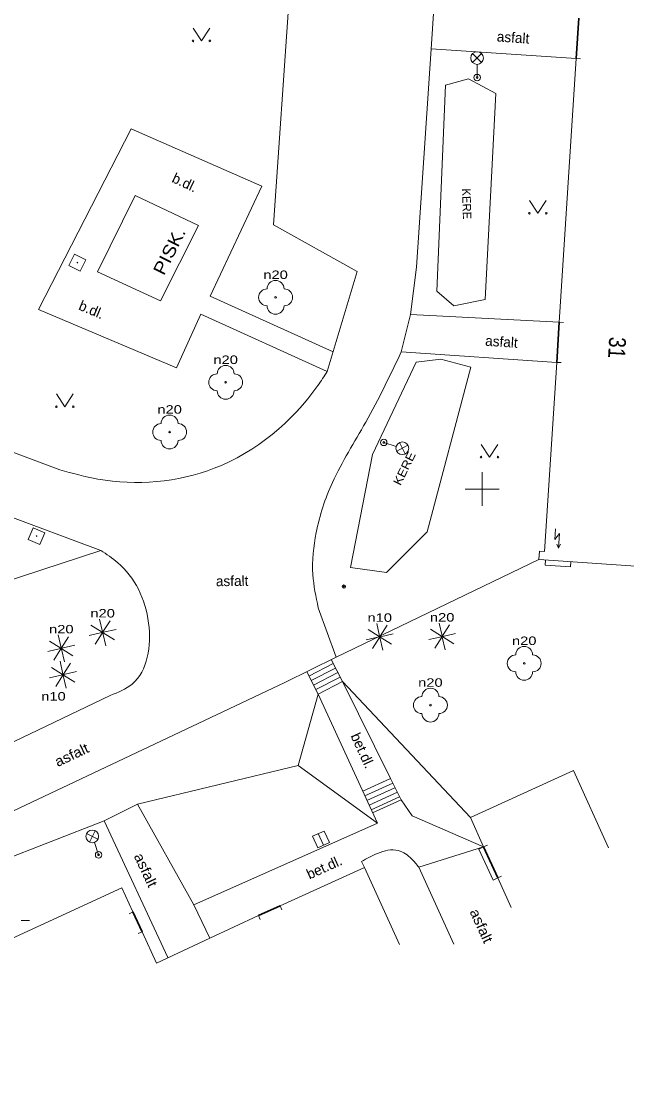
# Model space of a CAD drawing. Extents: x -670514 to -669423, y -1130798 to -1130123.
# Drawn here: x -670227.2 to -670191.5, y -1130334.6 to -1130272.3 of the extents above; entities that cross this region are included whole.
import ezdxf
from ezdxf.enums import TextEntityAlignment as Align

# ---------------------------------------------------------------- set-up
doc = ezdxf.new("R2010")
doc.units = 0
doc.header["$LTSCALE"] = 0.24
for name, color, linetype, lineweight in [('10', 7, 'Continuous', 13), ('11', 7, 'Continuous', 13), ('14', 7, 'Continuous', 13), ('21', 7, 'Continuous', 13), ('22', 7, 'Continuous', 13), ('24', 7, 'Continuous', 13), ('25', 7, 'Continuous', 13), ('26', 7, 'Continuous', 13), ('27', 7, 'Continuous', 13), ('28', 7, 'Continuous', 13), ('33', 7, 'Continuous', 13), ('36', 7, 'Continuous', 13), ('5', 7, 'Continuous', 13), ('6', 7, 'Continuous', 13), ('61', 7, 'Continuous', 13)]:
    doc.layers.add(name, color=color, linetype=linetype, lineweight=lineweight)
for name, color, linetype in [('40', 7, 'Continuous'), ('42', 7, 'Continuous'), ('44', 7, 'Continuous'), ('47', 7, 'Continuous')]:
    doc.layers.add(name, color=color, linetype=linetype)

msp = doc.modelspace()

# ---------------------------------------------------------------- linework, layer by layer
at = {"layer": '10'}
for p, q in [((-670212.326, -1130284.389), (-670210.077, -1130251.897)), ((-670203.011, -1130273.982), (-670202.849, -1130271.587)), ((-670203.011, -1130273.982), (-670194.444, -1130274.555)), ((-670212.326, -1130284.389), (-670207.379, -1130287.133)), ((-670266.711, -1130287.197), (-670222.534, -1130303.625)), ((-670209.153, -1130293.051), (-670207.379, -1130287.133)), ((-670204.781, -1130291.893), (-670204.232, -1130289.675)), ((-670204.232, -1130289.675), (-670195.447, -1130290.143)), ((-670224.952, -1130298.862), (-670248.531, -1130290.145)), ((-670204.781, -1130291.893), (-670195.588, -1130292.511)), ((-670208.8, -1130310.316), (-670210.24, -1130311.053)), ((-670208.254, -1130311.385), (-670208.918, -1130310.085)), ((-670209.694, -1130312.122), (-670210.369, -1130310.801)), ((-670208.664, -1130310.583), (-670210.104, -1130311.32)), ((-670208.527, -1130310.85), (-670209.967, -1130311.587)), ((-670208.391, -1130311.117), (-670209.83, -1130311.854)), ((-670208.254, -1130311.385), (-670209.694, -1130312.122)), ((-670260.508, -1130330.656), (-670221.974, -1130312.202)), ((-670207.059, -1130317.868), (-670205.41, -1130317.112)), ((-670206.933, -1130318.14), (-670205.284, -1130317.384)), ((-670206.808, -1130318.413), (-670205.159, -1130317.657)), ((-670206.683, -1130318.686), (-670205.014, -1130317.921)), ((-670206.558, -1130318.958), (-670204.882, -1130318.19)), ((-670206.475, -1130319.14), (-670204.794, -1130318.369)), ((-670222.341, -1130319.61), (-670220.36, -1130318.629)), ((-670218.564, -1130327.703), (-670222.341, -1130319.61)), ((-670200.194, -1130321.286), (-670199.921, -1130321.161)), ((-670200.194, -1130321.286), (-670199.354, -1130323.114)), ((-670207.125, -1130322.017), (-670206.96, -1130322.381)), ((-670201.684, -1130326.907), (-670203.753, -1130322.355)), ((-670199.354, -1130323.114), (-670199.08, -1130322.992))]:
    msp.add_line(p, q, dxfattribs=at)
for points in [[(-670204.232, -1130289.675), (-670203.879, -1130286.887), (-670203.011, -1130273.982)], [(-670209.153, -1130293.051), (-670216.624, -1130289.659), (-670218.068, -1130292.836), (-670226.221, -1130289.395), (-670220.741, -1130278.709), (-670213.028, -1130282.102), (-670216.077, -1130288.6), (-670208.805, -1130291.891)], [(-670250.355, -1130329.751), (-670211.664, -1130311.441), (-670208.625, -1130309.94), (-670209.689, -1130307.017)], [(-670208.254, -1130311.385), (-670205.41, -1130317.112), (-670204.794, -1130318.369), (-670204.134, -1130319.327), (-670199.921, -1130321.161)], [(-670217.034, -1130324.578), (-670206.19, -1130319.762), (-670209.694, -1130312.122)], [(-670216.085, -1130326.546), (-670217.034, -1130324.578), (-670220.36, -1130318.629)]]:
    msp.add_lwpolyline(points, dxfattribs=at)
msp.add_lwpolyline([(-670220.507, -1130282.648), (-670216.759, -1130284.417), (-670218.998, -1130288.876), (-670222.729, -1130287.157)], close=True, dxfattribs=at)
for points in [[(-670204.781, -1130291.893), (-670206.88, -1130296.047), (-670208.852, -1130299.618), (-670209.807, -1130302.573), (-670210.002, -1130305.061), (-670209.689, -1130307.017)], [(-670224.952, -1130298.862), (-670222.705, -1130299.41), (-670215.825, -1130298.771), (-670209.709, -1130293.883), (-670209.153, -1130293.051)], [(-670221.974, -1130312.202), (-670220.682, -1130311.529), (-670219.708, -1130307.923), (-670221.529, -1130304.354), (-670222.534, -1130303.625)], [(-670207.125, -1130322.017), (-670206.177, -1130321.537), (-670204.959, -1130321.371), (-670204.173, -1130321.862), (-670203.753, -1130322.355)]]:
    msp.add_spline(points, degree=3, dxfattribs=at)
at = {"layer": '11'}
msp.add_line((-670199.921, -1130321.161), (-670203.753, -1130322.355), dxfattribs=at)
at = {"layer": '14'}
for p, q in [((-670208.625, -1130309.94), (-670196.658, -1130304.168)), ((-670200.701, -1130319.409), (-670208.254, -1130311.385)), ((-670210.876, -1130316.337), (-670209.694, -1130312.122)), ((-670222.341, -1130319.61), (-670249.992, -1130330.449))]:
    msp.add_line(p, q, dxfattribs=at)
for points in [[(-670273.592, -1130303.857), (-670264.579, -1130298.061), (-670236.676, -1130308.269), (-670222.534, -1130303.625)], [(-670206.19, -1130319.762), (-670210.876, -1130316.337), (-670220.36, -1130318.629)]]:
    msp.add_lwpolyline(points, dxfattribs=at)
at = {"layer": '21'}
for points in [[(-670202.676, -1130288.295), (-670201.683, -1130289.165), (-670199.82, -1130288.792), (-670199.199, -1130276.615), (-670200.813, -1130275.745), (-670202.179, -1130276.117)], [(-670207.774, -1130304.642), (-670205.664, -1130304.936), (-670203.261, -1130302.531), (-670200.682, -1130292.796), (-670202.44, -1130292.327), (-670203.906, -1130292.503), (-670206.484, -1130297.957)]]:
    msp.add_lwpolyline(points, close=True, dxfattribs=at)
at = {"layer": '22'}
for p, q in [((-670222.43, -1130308.438), (-670222.602, -1130307.684)), ((-670221.988, -1130307.788), (-670222.402, -1130308.444)), ((-670206.061, -1130308.696), (-670206.233, -1130307.942)), ((-670202.374, -1130308.68), (-670202.546, -1130307.926)), ((-670224.872, -1130309.379), (-670225.044, -1130308.625)), ((-670223.216, -1130308.658), (-670222.462, -1130308.486)), ((-670222.456, -1130308.458), (-670223.112, -1130308.044)), ((-670222.442, -1130308.512), (-670222.856, -1130309.168)), ((-670222.414, -1130308.518), (-670222.242, -1130309.272)), ((-670221.732, -1130308.912), (-670222.388, -1130308.498)), ((-670222.382, -1130308.47), (-670221.628, -1130308.298)), ((-670206.087, -1130308.716), (-670206.743, -1130308.302)), ((-670205.619, -1130308.046), (-670206.033, -1130308.702)), ((-670206.013, -1130308.728), (-670205.259, -1130308.556)), ((-670202.4, -1130308.7), (-670203.056, -1130308.286)), ((-670201.932, -1130308.03), (-670202.346, -1130308.686)), ((-670202.326, -1130308.712), (-670201.572, -1130308.54)), ((-670224.898, -1130309.399), (-670225.554, -1130308.985)), ((-670224.43, -1130308.729), (-670224.844, -1130309.385)), ((-670224.824, -1130309.411), (-670224.07, -1130309.239)), ((-670206.847, -1130308.916), (-670206.093, -1130308.744)), ((-670206.073, -1130308.77), (-670206.487, -1130309.426)), ((-670206.045, -1130308.776), (-670205.873, -1130309.53)), ((-670205.363, -1130309.17), (-670206.019, -1130308.756)), ((-670203.16, -1130308.9), (-670202.406, -1130308.728)), ((-670202.386, -1130308.754), (-670202.8, -1130309.41)), ((-670202.358, -1130308.76), (-670202.186, -1130309.514)), ((-670201.676, -1130309.154), (-670202.332, -1130308.74)), ((-670225.658, -1130309.599), (-670224.904, -1130309.427)), ((-670224.884, -1130309.453), (-670225.298, -1130310.109)), ((-670224.856, -1130309.459), (-670224.684, -1130310.213)), ((-670224.174, -1130309.853), (-670224.83, -1130309.439)), ((-670224.768, -1130310.935), (-670224.94, -1130310.181)), ((-670224.326, -1130310.285), (-670224.74, -1130310.941)), ((-670225.554, -1130311.155), (-670224.8, -1130310.983)), ((-670224.794, -1130310.955), (-670225.45, -1130310.541)), ((-670224.78, -1130311.009), (-670225.194, -1130311.665)), ((-670224.752, -1130311.015), (-670224.58, -1130311.769)), ((-670224.07, -1130311.409), (-670224.726, -1130310.995)), ((-670224.72, -1130310.967), (-670223.966, -1130310.795))]:
    msp.add_line(p, q, dxfattribs=at)
for centre, radius in [((-670212.207, -1130288.667), 0.05), ((-670215.156, -1130293.69), 0.05), ((-670218.467, -1130296.63), 0.05), ((-670222.422, -1130308.478), 0.04), ((-670206.053, -1130308.736), 0.04), ((-670202.366, -1130308.72), 0.04), ((-670224.864, -1130309.419), 0.04), ((-670197.521, -1130310.305), 0.05), ((-670224.76, -1130310.975), 0.04), ((-670203.061, -1130312.774), 0.05)]:
    msp.add_circle(centre, radius, dxfattribs=at)
for centre, start, end in [((-670212.207, -1130288.167), 0, 180), ((-670212.707, -1130288.667), 90, 270), ((-670211.707, -1130288.667), 270, 90), ((-670212.207, -1130289.167), 180, 0), ((-670215.156, -1130293.19), 0, 180), ((-670215.656, -1130293.69), 90, 270), ((-670214.656, -1130293.69), 270, 90), ((-670215.156, -1130294.19), 180, 0), ((-670218.967, -1130296.63), 90, 270), ((-670218.467, -1130296.13), 0, 180), ((-670217.967, -1130296.63), 270, 90), ((-670218.467, -1130297.13), 180, 0), ((-670198.021, -1130310.305), 90, 270), ((-670197.521, -1130309.805), 0, 180), ((-670197.021, -1130310.305), 270, 90), ((-670197.521, -1130310.805), 180, 0), ((-670203.561, -1130312.774), 90, 270), ((-670203.061, -1130312.274), 0, 180), ((-670202.561, -1130312.774), 270, 90), ((-670203.061, -1130313.274), 180, 0)]:
    msp.add_arc(centre, 0.5, start, end, dxfattribs=at)
at = {"layer": '24'}
for points in [[(-670195.672, -1130302.362), (-670195.715, -1130302.986), (-670195.44, -1130302.629), (-670195.499, -1130303.502)], [(-670195.592, -1130303.25), (-670195.499, -1130303.502), (-670195.373, -1130303.265)], [(-670196.258, -1130304.195), (-670196.279, -1130304.494), (-670194.782, -1130304.595), (-670194.762, -1130304.296)]]:
    msp.add_lwpolyline(points, dxfattribs=at)
at = {"layer": '25'}
for radius in [0.1002, 0.0348]:
    msp.add_circle((-670208.172, -1130305.767), radius, dxfattribs=at)
at = {"layer": '26'}
for points in [[(-670224.417, -1130286.779), (-670223.747, -1130287.115), (-670223.411, -1130286.445), (-670224.081, -1130286.109)], [(-670226.521, -1130302.284), (-670226.817, -1130302.974), (-670226.127, -1130303.27), (-670225.831, -1130302.58)]]:
    msp.add_lwpolyline(points, close=True, dxfattribs=at)
for centre in [(-670223.9139, -1130286.612), (-670226.324, -1130302.7771)]:
    msp.add_circle(centre, 0.02, dxfattribs=at)
at = {"layer": '27'}
msp.add_line((-670209.684, -1130320.372), (-670209.372, -1130321.054), dxfattribs=at)
msp.add_lwpolyline([(-670210.024, -1130320.527), (-670209.712, -1130321.21), (-670209.03, -1130320.898), (-670209.342, -1130320.216)], close=True, dxfattribs=at)
at = {"layer": '28'}
msp.add_line((-670227.241, -1130325.511), (-670226.741, -1130325.511), dxfattribs=at)
at = {"layer": '33'}
for p, q in [((-670200.565, -1130274.26), (-670200.035, -1130274.79)), ((-670200.565, -1130274.79), (-670200.035, -1130274.26)), ((-670200.3, -1130275.675), (-670200.3, -1130274.9)), ((-670205.816, -1130297.244), (-670205.076, -1130297.476)), ((-670204.386, -1130297.414), (-670205.051, -1130297.761)), ((-670204.892, -1130297.256), (-670204.545, -1130297.92)), ((-670223.372, -1130320.37), (-670222.699, -1130320.699)), ((-670223.2, -1130320.871), (-670222.871, -1130320.198)), ((-670222.662, -1130321.622), (-670222.913, -1130320.889))]:
    msp.add_line(p, q, dxfattribs=at)
for centre, radius in [((-670200.3, -1130274.525), 0.375), ((-670200.3, -1130275.675), 0.19), ((-670200.3, -1130275.675), 0.05), ((-670205.816, -1130297.244), 0.19), ((-670205.816, -1130297.244), 0.05), ((-670204.7186, -1130297.5877), 0.375), ((-670223.0352, -1130320.5342), 0.375), ((-670222.662, -1130321.622), 0.19), ((-670222.662, -1130321.622), 0.05)]:
    msp.add_circle(centre, radius, dxfattribs=at)
at = {"layer": '36'}
for points in [[(-670217.085, -1130272.758), (-670216.585, -1130273.508), (-670216.085, -1130272.758)], [(-670197.215, -1130282.947), (-670196.715, -1130283.697), (-670196.215, -1130282.947)], [(-670225.157, -1130294.38), (-670224.657, -1130295.13), (-670224.157, -1130294.38)], [(-670200.072, -1130297.362), (-670199.572, -1130298.112), (-670199.072, -1130297.362)]]:
    msp.add_lwpolyline(points, dxfattribs=at)
for centre in [(-670217.085, -1130273.508), (-670216.085, -1130273.508), (-670197.215, -1130283.697), (-670196.215, -1130283.697), (-670225.157, -1130295.13), (-670224.157, -1130295.13), (-670200.072, -1130298.112), (-670199.072, -1130298.112)]:
    msp.add_circle(centre, 0.05, dxfattribs=at)
at = {"layer": '5'}
for p, q in [((-670195.447, -1130290.143), (-670194.444, -1130274.555)), ((-670195.588, -1130292.511), (-670196.325, -1130303.689)), ((-670196.624, -1130303.669), (-670196.658, -1130304.168)), ((-670196.658, -1130304.168), (-670184.928, -1130304.963)), ((-670196.325, -1130303.689), (-670196.624, -1130303.669)), ((-670192.541, -1130321.203), (-670194.604, -1130316.648)), ((-670211.933, -1130324.641), (-670206.96, -1130322.381)), ((-670204.891, -1130326.933), (-670206.96, -1130322.381)), ((-670199.08, -1130322.992), (-670198.3, -1130324.744)), ((-670221.281, -1130323.579), (-670245.25, -1130334.578)), ((-670221.281, -1130323.579), (-670220.637, -1130324.999))]:
    msp.add_line(p, q, dxfattribs=at)
for points in [[(-670194.604, -1130316.648), (-670200.701, -1130319.409), (-670199.921, -1130321.161)], [(-670220.096, -1130326.173), (-670219.25, -1130328.023), (-670216.085, -1130326.546), (-670213.224, -1130325.219)]]:
    msp.add_lwpolyline(points, dxfattribs=at)
at = {"layer": '6', "lineweight": 35}
for p, q in [((-670194.302, -1130272.164), (-670194.444, -1130274.555)), ((-670195.447, -1130290.143), (-670195.588, -1130292.511)), ((-670199.921, -1130321.161), (-670199.08, -1130322.992)), ((-670211.933, -1130324.641), (-670213.224, -1130325.219)), ((-670220.096, -1130326.173), (-670220.637, -1130324.999))]:
    msp.add_line(p, q, dxfattribs=at)
at = {"layer": '6'}
for p, q in [((-670194.194, -1130274.569), (-670194.444, -1130274.555)), ((-670195.447, -1130290.143), (-670195.197, -1130290.157)), ((-670195.338, -1130292.525), (-670195.588, -1130292.511)), ((-670199.921, -1130321.161), (-670199.693, -1130321.056)), ((-670198.852, -1130322.887), (-670199.08, -1130322.992)), ((-670211.933, -1130324.641), (-670211.83, -1130324.869)), ((-670220.864, -1130325.103), (-670220.637, -1130324.999)), ((-670213.121, -1130325.447), (-670213.224, -1130325.219)), ((-670220.096, -1130326.173), (-670220.323, -1130326.277))]:
    msp.add_line(p, q, dxfattribs=at)
at = {"layer": '61'}
for p, q in [((-670200, -1130301), (-670200, -1130299)), ((-670201, -1130300), (-670199, -1130300))]:
    msp.add_line(p, q, dxfattribs=at)

# ---------------------------------------------------------------- texts
at = {"layer": '22', "width": 1.3}
for s, p in [('n20', (-670212.2065, -1130287.581)), ('n20', (-670215.1555, -1130292.604)), ('n20', (-670218.4665, -1130295.544)), ('n20', (-670222.4225, -1130307.592)), ('n10', (-670206.0535, -1130307.85)), ('n20', (-670202.3665, -1130307.834)), ('n20', (-670224.8645, -1130308.533)), ('n20', (-670197.5205, -1130309.219)), ('n20', (-670203.0605, -1130311.688)), ('n10', (-670225.3275, -1130312.503))]:
    msp.add_text(s, height=0.499, dxfattribs=at).set_placement(p, align=Align.CENTER)
at = {"layer": '40'}
for s, rotation, p in [('asfalt', 356.173, (-670198.196, -1130273.6027)), ('b.dl.', 334.733, (-670217.6965, -1130282.1521)), ('b.dl.', 337.118, (-670223.1962, -1130289.6723)), ('asfalt', 356.154, (-670198.8831, -1130291.5881)), ('asfalt', 0.671, (-670214.77, -1130305.7339)), ('bet.dl.', 294.638, (-670207.3372, -1130315.5824)), ('bet.dl.', 24.44, (-670209.2116, -1130322.6352))]:
    msp.add_text(s, height=0.6, rotation=rotation, dxfattribs=at).set_placement(p, align=Align.CENTER)
at = {"layer": '40', "width": 1.1}
for rotation, p in [(25.325, (-670224.1253, -1130315.9862)), (295.018, (-670220.1475, -1130322.6541)), (294.443, (-670200.3201, -1130325.9439))]:
    msp.add_text('asfalt', height=0.6, rotation=rotation, dxfattribs=at).set_placement(p, align=Align.CENTER)
at = {"layer": '42', "width": 1.15}
msp.add_text('PISK.', height=0.75, rotation=63.337, dxfattribs=at).set_placement((-670218.1446, -1130286.0998), align=Align.CENTER)
at = {"layer": '44', "width": 0.85}
msp.add_text('31', height=1, rotation=266.592, dxfattribs=at).set_placement((-670192.5302, -1130291.6143), align=Align.CENTER)
at = {"layer": '47'}
msp.add_text('KERE', height=0.5, rotation=271.811, dxfattribs=at).set_placement((-670201.1649, -1130283.1461), align=Align.CENTER)
at = {"layer": '47', "width": 1.15}
msp.add_text('KERE', height=0.5, rotation=63.797, dxfattribs=at).set_placement((-670204.3715, -1130298.8944), align=Align.CENTER)

doc.saveas('drawing.dxf')
